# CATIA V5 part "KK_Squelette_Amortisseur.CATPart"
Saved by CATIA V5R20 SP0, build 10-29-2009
Part number: Squelette_corps_amortisseur
Bounding box of the stored display mesh (mm): x -200 to 200, y 640 to 1632, z -2292 to -320
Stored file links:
  G:\Khaled_CFAO_2011\ST2M\ST2M_GR2\aboulegue\Khaled\CAD_thinkMOTION\KK_Squelette_Amortisseur.CATPart
  G:\Khaled_CFAO_2011\ST2M\ST2M_GR2\aboulegue\Khaled\CAD_thinkMOTION\KK_Train_Atterrissage.CATProduct
  G:\Khaled_CFAO_2011\ST2M\ST2M_GR2\aboulegue\CFAO_aboulegue\CFAO_aboulegue_fichiers_catia\Squelette_general.CATPart
  G:\Khaled_CFAO_2011\ST2M\ST2M_GR2\aboulegue\Khaled\CAD_thinkMOTION\KK_SqueletteCompas_Superieur.CATPart
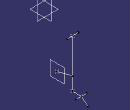
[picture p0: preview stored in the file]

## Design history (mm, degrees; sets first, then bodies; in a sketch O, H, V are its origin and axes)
Set1
  Point1: linked copy from another document
  Plane1 "Plan reference": linked copy from another document
  Point2: linked copy from another document
  Point3: linked copy from another document
  Point4 "Point.14": linked copy from another document
  Line1: linked copy from another document
Set2 "Set_squelette_corps_amortisseur"
  Line2: type PtPt, FirstPoint Point1, SecondPoint Point4
  Line3: type PtPt, FirstPoint Point3, SecondPoint Point4
  Line4: type Angle, LineFirstUpto Point2, LineSecondUpto Line2, Start -200, End 200, Angle 90
  Line5: type Normal, RefPoint Point1, RefSkin Plane1, Start -200, End 200
  Line6: type Normal, RefPoint Point3, RefSkin Plane1, Start -200, End 200
  Plane2 "Plan corps amortisseur": type OffsetPt, RefPlane Plane1, RefPoint Point2
Body1 (main body)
